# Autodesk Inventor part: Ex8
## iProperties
Author: Administrator
Created: 2001-01
Part Number: Ex8
Material: Stainless Steel, Austenitic
Document SubType Name: Sheet Metal
Designer: Administrator
Control State: 0
Master: False
Checked Out: False
PropertySet Name: Design Tracking Control
Shininess: 60.0
PropertySet Name: _Private Model Information
Density: 0.0
Volumn: 0.0
Area: 0.0
PropertySet Name: Model Information
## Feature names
1. Corner Chamfer1
2. Hole1
3. Hole2
4. Rectangular Pattern1
5. Hole3
6. Extrusion1
7. Fillet1
8. Fillet2
9. Corner Round1
10. Cut1
11. Plate1
12. Plate2
13. Bend1
